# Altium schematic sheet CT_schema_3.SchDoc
size 199 x 169 mm
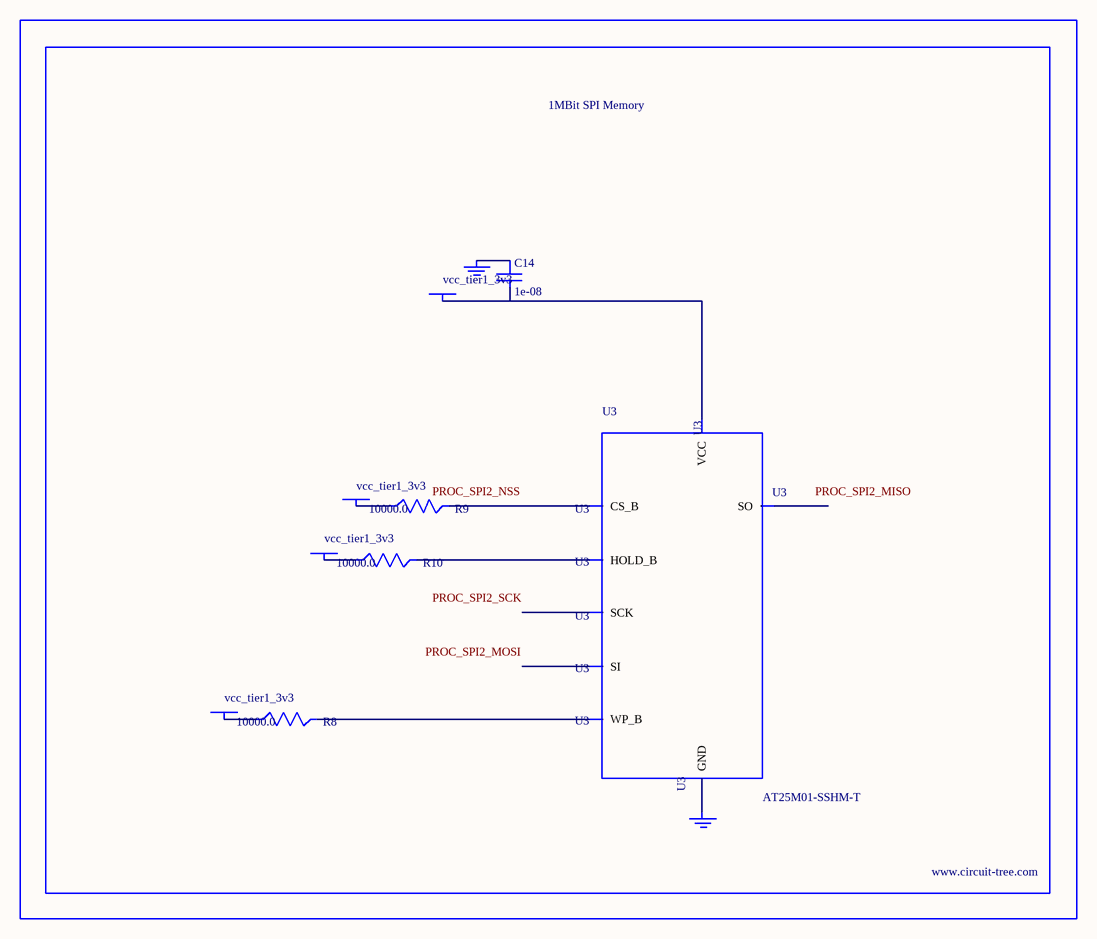
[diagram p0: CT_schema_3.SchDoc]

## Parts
BORDER2  (no value)
C14  1e-08  [C0402]
GND_INSTANCE_2_0  (no value)
GND_INSTANCE_2_1  (no value)
POWER_INSTANCE_2_0  vcc_tier1_3v3
POWER_INSTANCE_2_1  vcc_tier1_3v3
POWER_INSTANCE_2_2  vcc_tier1_3v3
POWER_INSTANCE_2_3  vcc_tier1_3v3
R8  10000.0  [R0603]
R9  10000.0  [R0603]
R10  10000.0  [R0603]
U3  AT25M01-SSHM-T  [SOIC-8]

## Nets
NetC14_1: C14.1 GND_INSTANCE_2_0.0(GND)
NetC14_2: C14.2 POWER_INSTANCE_2_3.0(PWR) U3.8(VCC)
NetGND_INSTANCE_2_1_0: GND_INSTANCE_2_1.0(GND) U3.4(GND)
NetPOWER_INSTANCE_2_0_0: POWER_INSTANCE_2_0.0(PWR) R9.1
NetPOWER_INSTANCE_2_1_0: POWER_INSTANCE_2_1.0(PWR) R8.1
NetPOWER_INSTANCE_2_2_0: POWER_INSTANCE_2_2.0(PWR) R10.1
NetR8_2: R8.2 U3.3(WP_B)
NetR9_2: R9.2 U3.1(CS_B)
NetR10_2: R10.2 U3.7(HOLD_B)

Not connected (* = marked no-connect by the designer): U3 2(SO) 5(SI) 6(SCK)

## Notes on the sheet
- Labels drawn without touching a wire or pin: PROC_SPI2_MISO, PROC_SPI2_MOSI, PROC_SPI2_NSS, PROC_SPI2_SCK

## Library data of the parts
BORDER2 = BORDER_PAGE2
C14 = C0402C103K3RAC
GND_INSTANCE_2_0 GND_INSTANCE_2_1 = GND
POWER_INSTANCE_2_0-POWER_INSTANCE_2_3 = PWR
R8-R10 = RC0603JR-0710KL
